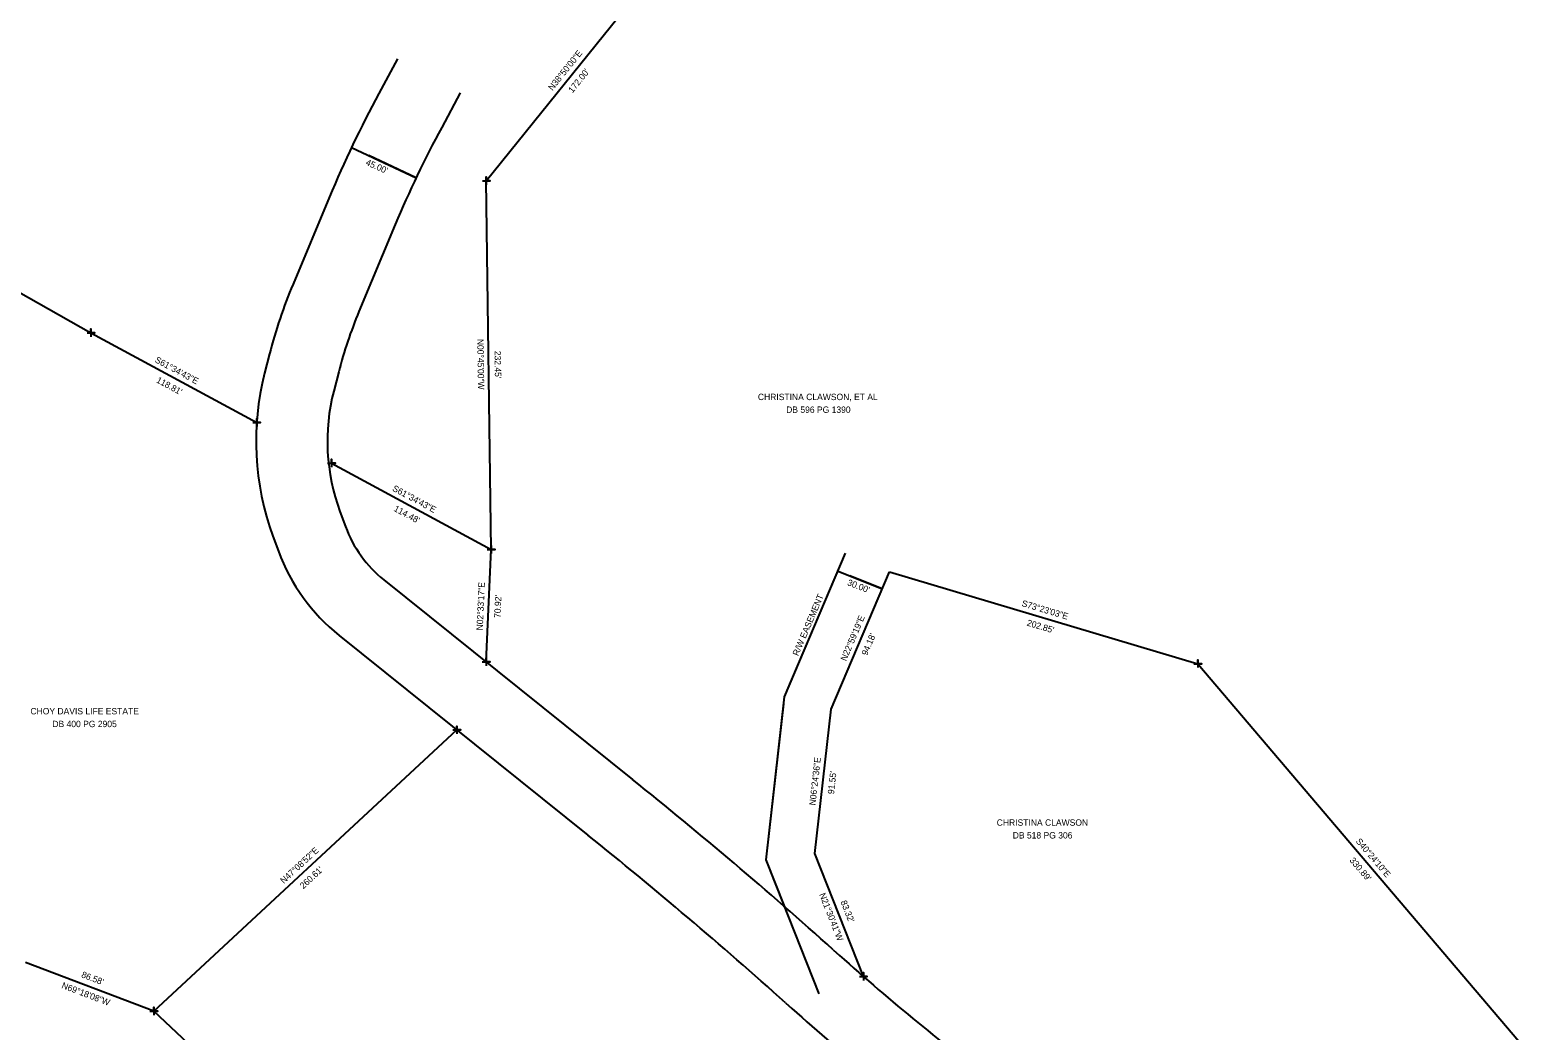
# Model space of a CAD drawing. Extents: x 1121294 to 1124558, y 901107 to 903080.
# Drawn here: x 1122827 to 1123778, y 901468 to 902098 of the extents above; entities that cross this region are included whole.
import ezdxf

# ---------------------------------------------------------------- set-up
doc = ezdxf.new("R2010")
doc.units = 0
for name, color, linetype in [('CTL Primary Horizontal and Vertical CELL', 7, 'Continuous'), ('CTL Secondary Horizontal and Vertical CELL', 7, 'Continuous'), ('CTL Vertical Benchmark CELL', 7, 'Continuous'), ('Default Symbol CELL', 7, 'Continuous'), ('Exist DTM Regular Point CELL', 7, 'Continuous'), ('Exist Survey Control Group', 7, 'Continuous'), ('Exist Survey Observation Group', 7, 'Continuous'), ('Exist Utilities Power Pole CELL', 7, 'Continuous')]:
    doc.layers.add(name, color=color, linetype=linetype)

msp = doc.modelspace()

# ---------------------------------------------------------------- linework, layer by layer
at = {"layer": 'CTL Secondary Horizontal and Vertical CELL'}
for p, q in [((1121412.43, 902728.23), (1122865.6, 901907.59)), ((1123114.89, 902003.46), (1123222.74, 902137.44)), ((1123117.93, 901771.03), (1123114.89, 902003.46)), ((1122865.6, 901907.59), (1122970.09, 901851.04)), ((1123017.25, 901825.51), (1123117.93, 901771.03)), ((1123114.77, 901700.18), (1123117.93, 901771.03)), ((1123332.29, 901670.38), (1123369.07, 901757.08)), ((1123369.07, 901757.08), (1123563.45, 901699.08)), ((1123563.45, 901699.08), (1123777.92, 901447.1)), ((1123322.07, 901579.41), (1123332.29, 901670.38)), ((1122905.29, 901480.03), (1123096.34, 901657.27)), ((1123352.62, 901501.89), (1123322.07, 901579.41)), ((1122905.29, 901480.03), (1122824.3, 901510.63)), ((1123299.8, 901109.21), (1122905.29, 901480.03))]:
    msp.add_line(p, q, dxfattribs=at)
at = {"layer": 'CTL Vertical Benchmark CELL'}
for p, q in [((1123114.89, 902003.46), (1123114.89, 902003.46)), ((1122865.6, 901907.59), (1122865.6, 901907.59)), ((1122970.09, 901851.04), (1122970.09, 901851.04)), ((1123017.25, 901825.51), (1123017.25, 901825.51)), ((1123117.93, 901771.03), (1123117.93, 901771.03)), ((1123114.77, 901700.18), (1123114.77, 901700.18)), ((1123563.45, 901699.08), (1123563.45, 901699.08)), ((1123096.34, 901657.27), (1123096.34, 901657.27)), ((1123352.62, 901501.89), (1123352.62, 901501.89)), ((1122905.29, 901480.03), (1122905.29, 901480.03))]:
    msp.add_line(p, q, dxfattribs=at)
for points in [[(1123112.39, 902003.46), (1123117.39, 902003.46), (1123114.89, 902003.46), (1123114.89, 902005.96), (1123114.89, 902000.96)], [(1122863.1, 901907.59), (1122868.1, 901907.59), (1122865.6, 901907.59), (1122865.6, 901910.09), (1122865.6, 901905.09)], [(1122967.59, 901851.04), (1122972.59, 901851.04), (1122970.09, 901851.04), (1122970.09, 901853.54), (1122970.09, 901848.54)], [(1123014.75, 901825.51), (1123019.75, 901825.51), (1123017.25, 901825.51), (1123017.25, 901828.01), (1123017.25, 901823.01)], [(1123115.43, 901771.03), (1123120.43, 901771.03), (1123117.93, 901771.03), (1123117.93, 901773.53), (1123117.93, 901768.53)], [(1123112.27, 901700.18), (1123117.27, 901700.18), (1123114.77, 901700.18), (1123114.77, 901702.68), (1123114.77, 901697.68)], [(1123560.95, 901699.08), (1123565.95, 901699.08), (1123563.45, 901699.08), (1123563.45, 901701.58), (1123563.45, 901696.58)], [(1123093.84, 901657.27), (1123098.84, 901657.27), (1123096.34, 901657.27), (1123096.34, 901659.77), (1123096.34, 901654.77)], [(1123350.12, 901501.89), (1123355.12, 901501.89), (1123352.62, 901501.89), (1123352.62, 901504.39), (1123352.62, 901499.39)], [(1122902.79, 901480.03), (1122907.79, 901480.03), (1122905.29, 901480.03), (1122905.29, 901482.53), (1122905.29, 901477.53)]]:
    msp.add_lwpolyline(points, dxfattribs=at)
at = {"layer": 'Default Symbol CELL'}
for p, q in [((1123058.92, 902080.29), (1123047.16, 902058.56)), ((1123015.96, 901993.28), (1122993.02, 901938.38)), ((1122978.25, 901894.34), (1122975.11, 901882.15)), ((1122980.37, 901779.42), (1122983.88, 901769.91)), ((1123304.67, 901682.1), (1123341.45, 901768.8)), ((1123022.13, 901716.81), (1123178.91, 901591.02)), ((1123292.26, 901582.76), (1123302.48, 901673.73)), ((1123324.71, 901490.89), (1123294.16, 901568.41)), ((1123303.55, 901485.27), (1123307.51, 901481.71))]:
    msp.add_line(p, q, dxfattribs=at)
for centre, radius, start, end in [((1123682.61, 901714.74), 722.5, 151.58353, 157.32371), ((1123290.59, 901814.05), 322.5, 157.32371, 165.58322), ((1123142.18, 901839.2), 172.5, 165.58322, 200.27724), ((1123098.79, 901812.36), 122.5, 200.27724, 231.2586), ((1121315.57, 899268.64), 2977.5, 48.11275, 51.2586), ((1124324.04, 902615.15), 1522.5, 228.11275, 233.15592)]:
    msp.add_arc(centre, radius, start, end, dxfattribs=at)
at = {"layer": 'Exist DTM Regular Point CELL'}
for p, q in [((1123098.49, 902058.87), (1123086.74, 902037.14)), ((1123057.48, 901975.93), (1123034.54, 901921.03)), ((1123021.83, 901883.14), (1123018.69, 901870.94)), ((1123022.58, 901795.01), (1123026.09, 901785.5)), ((1123302.96, 901678.07), (1123341.45, 901768.8)), ((1123050.29, 901751.91), (1123207.07, 901626.12)), ((1123291.42, 901575.35), (1123302.96, 901678.07)), ((1123303.08, 901545.76), (1123291.42, 901575.35)), ((1123333.6, 901518.77), (1123337.56, 901515.21))]:
    msp.add_line(p, q, dxfattribs=at)
for centre, radius, start, end in [((1123682.61, 901714.74), 677.5, 151.58353, 157.32371), ((1123290.59, 901814.05), 277.5, 157.32371, 165.58322), ((1123142.18, 901839.2), 127.5, 165.58322, 200.27724), ((1123098.79, 901812.36), 77.5, 200.27724, 231.2586), ((1121315.57, 899268.64), 3022.5, 48.11275, 51.2586), ((1124324.04, 902615.15), 1477.5, 228.11275, 233.15592)]:
    msp.add_arc(centre, radius, start, end, dxfattribs=at)
at = {"layer": 'Exist Survey Control Group'}
for p, q in [((1123029.85, 902024.43), (1123070.65, 902005.38)), ((1123070.61, 902005.37), (1123040.75, 902019.34)), ((1123336.66, 901757.5), (1123364.49, 901746.28)), ((1123364.48, 901746.25), (1123344.15, 901754.47))]:
    msp.add_line(p, q, dxfattribs=at)

# ---------------------------------------------------------------- texts
at = {"layer": 'CTL Primary Horizontal and Vertical CELL'}
for s, rotation, p in [("45.00'", 336.17002, (1123038.43, 902013.64)), ("30.00'", 339.22803, (1123342.13, 901748.66))]:
    msp.add_text(s, height=4.02, rotation=rotation, dxfattribs=at).set_placement(p)
at = {"layer": 'Exist DTM Regular Point CELL'}
msp.add_text('N21°30\'41"W', height=4.02, rotation=291.51149, dxfattribs=at).set_placement((1123324.7, 901553.58))
at = {"layer": 'Exist Survey Observation Group'}
for s, rotation, p in [('N38°50\'00"E', 51.16667, (1123156.59, 902060.04)), ("172.00'", 51.16667, (1123169.26, 902058.56)), ('N00°45\'00"W', 270.75, (1123109.17, 901903.82)), ("232.45'", 270.75, (1123120.07, 901896.28)), ('S61°34\'43"E', 331.57869, (1122905.53, 901889.39)), ("118.81'", 331.57869, (1122906.41, 901876.63)), ('S61°34\'43"E', 331.57869, (1123055.28, 901808.34)), ("114.48'", 331.57869, (1123056.16, 901795.59)), ('N02°33\'17"E', 87.44542, (1123112.65, 901719.98)), ("70.92'", 87.44542, (1123123.81, 901727.83)), ('S73°23\'03"E', 343.38421, (1123452.15, 901735.42)), ('N22°59\'19"E', 67.01147, (1123341.76, 901700.38)), ("202.85'", 343.38421, (1123455.41, 901723.18)), ("94.18'", 67.01147, (1123354.96, 901703.85)), ('N06°24\'36"E', 83.59006, (1123322.44, 901609.55)), ("91.55'", 83.59006, (1123334.1, 901616.64)), ('N47°08\'52"E', 42.8523, (1122987.21, 901560.12)), ('S40°24\'10"E', 310.40275, (1123662.84, 901586.93)), ("260.61'", 42.8523, (1122999.53, 901556.82)), ("330.89'", 310.40275, (1123658.92, 901574.88)), ("83.32'", 291.51149, (1123338.14, 901548.94)), ("86.58'", 339.3023, (1122859.18, 901501.49)), ('N69°18\'08"W', 339.3023, (1122846.72, 901494.65))]:
    msp.add_text(s, height=4.02, rotation=rotation, dxfattribs=at).set_placement(p)
for s, p in [('CHRISTINA CLAWSON, ET AL', (1123286.12, 901865.23)), ('DB 596 PG 1390', (1123303.95, 901857.19)), ('CHOY DAVIS LIFE ESTATE', (1122827.44, 901667.11)), ('DB 400 PG 2905', (1122841.24, 901659.07)), ('CHRISTINA CLAWSON', (1123436.71, 901596.9)), ('DB 518 PG 306', (1123446.8, 901588.86))]:
    msp.add_text(s, height=4.02, dxfattribs=at).set_placement(p)
at = {"layer": 'Exist Utilities Power Pole CELL'}
msp.add_text('R/W EASEMENT', height=4.02, rotation=67.01147, dxfattribs=at).set_placement((1123311.49, 901703.62))

doc.saveas('drawing.dxf')
